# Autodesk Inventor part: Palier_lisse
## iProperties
Shininess: 64.0
Length Units: 11269
Angle Units: 11279
Time Units: 11290
Mass Units: 11283
Length Display Precision: 3
Angle Display Precision: 2
Compacted: True
Part Number: Palier_lisse
Document SubType Name: Modeling
Created: 2008-02
Material: Bronze (étain doux)
Designer: Pascal
Density: 0.0
Volumn: 0.0
Area: 0.0
PropertySet Name: Model Information
Control State: 0
Master: False
Checked Out: False
DESIGNATION: pièce
Author: Pascal
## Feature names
1. Révolution1 [Revolution]
2. Chanfrein1 [Chamfer]
